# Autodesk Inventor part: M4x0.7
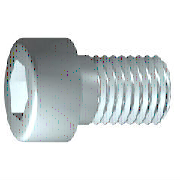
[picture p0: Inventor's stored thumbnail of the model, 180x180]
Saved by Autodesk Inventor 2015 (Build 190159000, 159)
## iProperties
IsCustomPart: 1
Created: 2015-10
Part Number: M4x0.7
Material: Steel, Mild
Description: 6각머리 태핑 나사
Document SubType Name: Modeling
Standard: KS B 1003
Designer: mdu
Standards Organization: KS
Language: ko-KR
Size Designation: M 4 x 16
Categories: <MemberInstance><Categories><Category DisplayName="조임쇠" InternalName="e4da775c-781d-43d5-af7c-5136215cf5a6" Mnemonic="FSTN"><Category DisplayName="볼트" InternalN
Density: 7.85 g/cm^3
Appearance: Steel
Mass: 2.62639 g
Surface Area: 3.81118 cm^2
Volume: 0.334572 cm^3
Author: mdu
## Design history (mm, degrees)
revolve "본체" stored, may be unused: angle "d10" = 90 deg
sketch "스케치2"
  geometry: L1 (0, -4.9)-(0, 4.9) reference; L2 (-4.9, 0)-(4.9, 0) reference; L3 (1.732, 0)-(0.866, -1.5); L4 (0.866, -1.5)-(-0.866, -1.5); L5 (-0.866, -1.5)-(-1.732, 0); L6 (-1.732, 0)-(-0.866, 1.5); L7 (-0.866, 1.5)-(0.866, 1.5); L8 (0.866, 1.5)-(1.732, 0); 2 further points
  constraints: 12 end point, 1 coincident, 1 horizontal alignment, 1 point on line, 12 other
extrude "슬롯" join sketch "스케치2" stored distance "d11" = 10; taper "d12" = 0 deg
workplane "Work Plane1"
fillet "Fillet2" dims "d30" = 0.1 (= R)
body "Solid1"
fillet "모깎기1" dims "d17" = 0.4 (= RR)
feature "스레드" dims "d13" = 14.25 (= GEL), "d14" = 0
chamfer "모따기1" distance "d15" = 0.42941 (= -0.5 x SPD + 0.5 x GD); stored, may be unused: second distance "d16" = 0.42941 (= GUL), angle "d27" = 45 deg
sketch "스케치1"
  geometry: L1 (-1, 0)-(16, 0); L2 (16, 0)-(16, 2); L3 (16, 2)-(1.75, 2); L4 (1.75, 2)-(1.32, 2); L5 (1.32, 2)-(0, 2); L6 (0, 2)-(0, 3.5); L7 (0, 3.5)-(-4, 3.5); L8 (-4, 3.5)-(-4, 1.732); L9 (-4, 1.732)-(-2, 1.732); L10 (-2, 1.732)-(-1, 0); L11 (-8, 0)-(20, 0) reference; L12 (0, -0.7)-(0, 4.2) reference; L13 (1.75, 2)-(0, 2)
  constraints: 22 end point, 6 parallel, 2 collinear, 2 perpendicular, 1 horizontal, 1 point on line
  dimensions: "d1" = 14.25 distance from line of L3.end L2 (= GEL); "d2" = 0.42952 distance of L4.end L3.end (computed from GAL); "d3" = 4 distance between parallel lines of L8 L6 (= KOH); "d4" = 2 distance of L8.end L9.end (= INTI); "d5" = 60 deg angle of L10 L1; "d6" = 4 diameter of L3 L1 (= GD); "d7" = 4 diameter of L5 L1 (= BDM); "d8" = 3.4641 diameter of L9 L1 (= 1.1547 x SW); "d9" = 7 diameter of L7 L1 (= KOD); "d26" = 16 distance between parallel lines of L12 L2 (= NLG)
other parameters: "GD" = 4 (= NND) [user parameter; used in 2 equation terms], "NLG" = 16 [user parameter; used in 1 equation term], "GEL" = 14.25 [user parameter; used in 2 equation terms], "KOD" = 7 [user parameter; used in 1 equation term], "KOH" = 4 [user parameter; used in 1 equation term], "INTI" = 2 [user parameter; used in 1 equation term], "GAL" = 0.42941 (= 0.61345 x PTC) [user parameter; used in 1 equation term], "GUL" = 0.42941 (= 0.61345 x PTC) [user parameter; used in 1 equation term], "BDM" = 4 (= NND) [user parameter; used in 1 equation term], "SW" = 3 [user parameter; used in 2 equation terms], "RR" = 0.4 [user parameter; used in 1 equation term], "SPD" = 3.14117 (= NND - 1.2269 x PTC) [user parameter; used in 1 equation term], "d19" = 0, "d28" = 0, "d29" = 0, "R" = 0.1 [user parameter; used in 1 equation term], "PHH" = 0.2 [user parameter], "GD1" = 3.14117 (= THREADDIA - 1.2269 x PTC) [user parameter], "THREADDIA" = 4 [user parameter; used in 1 equation term], "FAWI" = 45 deg [user parameter], "TPU" = 14.28571 (computed from PTC) [user parameter], "PTC" = 0.7 [user parameter; used in 5 equation terms], "NND" = 4 [user parameter; used in 3 equation terms], "TOA" = 30 deg [user parameter], "E0" = 3.465 (= 1.155 x SW) [user parameter]
